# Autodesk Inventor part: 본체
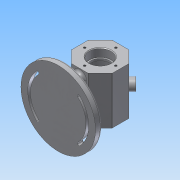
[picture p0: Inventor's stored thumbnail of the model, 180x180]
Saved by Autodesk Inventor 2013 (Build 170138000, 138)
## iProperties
Created: 2017-06
Part Number: 본체
Material: 알루미늄 6061
Document SubType Name: Modeling
Designer: Administrator
Density: 2.71 g/cm^3
Mass: 562.243 g
Surface Area: 566.157 cm^2
Volume: 207.47 cm^3
Author: Administrator
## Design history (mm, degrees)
sketch "스케치1"
  geometry: L1 (12.426, 30)-(30, 12.426); L2 (30, 12.426)-(30, -12.426); L3 (30, -12.426)-(12.426, -30); L4 (12.426, -30)-(-12.426, -30); L5 (-12.426, -30)-(-30, -12.426); L6 (-30, -12.426)-(-30, 12.426); L7 (-30, 12.426)-(-12.426, 30); L8 (-12.426, 30)-(12.426, 30); 2 further points
  constraints: 16 end point, 1 coincident, 1 horizontal, 17 other
  dimensions: "d0" = 60 distance between parallel lines of L3 L7
extrude "돌출1" new body sketch "스케치1" stored distance "d1" = 70; taper "d2" = 0 deg
sketch "스케치2"
  geometry: C1 r 25 at (0, 0); 1 further point
  constraints: 1 centre point, 1 coincident
  dimensions: "d3" = 50 diameter of C1
extrude "돌출2" cut sketch "스케치2" stored distance "d4" = 40; taper "d5" = 0 deg
sketch "스케치3"
  geometry: 2 further points
  constraints: 1 coincident
hole "구멍1" sketch "스케치3" at (0, 0) diameter "d6" = 28; stored, may be unused: countersink angle "d10" = 90 deg, drill point angle "d12" = 0 deg; dims "d7" = 6, "d8" = 32, "d9" = 12, "d11" = 15
node "작업 평면1"
sketch "스케치4"
  geometry: C1 r 8 at (-12.426, 35); 1 further point
  constraints: 1 centre point, 1 coincident
  dimensions: "d14" = 16 diameter of C1
extrude "돌출3" join sketch "스케치4" stored distance "d16" = 40; taper "d17" = 0 deg
node "작업 평면2"
sketch "스케치5"
  geometry: C1 r 55 at (0, 0); 1 further point
  constraints: 1 centre point, 1 coincident
  dimensions: "d19" = 110 diameter of C1
extrude "돌출4" join sketch "스케치5" distance "d20" = 10; taper "d21" = 0 deg
fillet "모깎기1" dims "d22" = 3
sketch "스케치6"
  geometry: C1 r 52 at (0, 0) reference; A1 r 48 centre (0, 0) between (-33.941, 33.941) and (-33.941, -33.941); A2 r 38 centre (0, 0) between (-26.87, 26.87) and (-26.87, -26.87); A3 r 5 centre (-30.406, 30.406) between (-26.87, 26.87) and (-33.941, 33.941); A4 r 5 centre (-30.406, -30.406) between (-33.941, -33.941) and (-26.87, -26.87); A5 r 2 centre (-30.406, -30.406) between (-31.82, -31.82) and (-28.991, -28.991); A6 r 2 centre (-30.406, 30.406) between (-28.991, 28.991) and (-31.82, 31.82); A7 r 41 centre (0, 0) between (-28.991, 28.991) and (-28.991, -28.991); A8 r 45 centre (0, 0) between (-31.82, 31.82) and (-31.82, -31.82)
  constraints: 16 point on circle, 8 centre point, 6 coincident, 6 tangent, 1 vertical alignment
  dimensions: "d23" = 96 diameter of A1; "d24" = 76 diameter of A2; "d25" = 90 deg dimension on C1.centre A4.centre A3.centre; "d26" = 2 radius of A5; "d27" = 2 radius of A6
extrude "돌출5" cut sketch "스케치6" distance "d28" = 3; taper "d29" = 0 deg
extrude "돌출6" cut sketch "스케치6" stored distance "d30" = 3; taper "d31" = 0 deg
sketch "스케치7"
  geometry: L1 (-5, -24)-(5, -24); L2 (5, -24)-(5, 24); L3 (5, 24)-(-5, 24); L4 (-5, 24)-(-5, -24); L5 (-5, -24)-(5, 24); L6 (5, -24)-(-5, 24); C1 r 52 at (0, 0) reference; 2 further points
  constraints: 12 end point, 4 midpoint, 2 horizontal alignment, 2 parallel, 1 horizontal, 1 perpendicular, 4 other
  dimensions: "d32" = 10 distance of L3.end L2.end; "d33" = 48 distance of L2.end L1.end
extrude "돌출7" join sketch "스케치7" stored distance "d34" = 3; taper "d35" = 0 deg
fillet "모깎기2" dims "d36" = 5
sketch "스케치8"
  geometry: C1 r 8 at (0, 0) reference; C2 r 4 at (0, 0)
  constraints: 1 centre point, 1 coincident
  dimensions: "d37" = 8 diameter of C2
extrude "돌출8" cut sketch "스케치8" stored distance "d38" = 3; taper "d39" = 0 deg
chamfer "모따기1" distance "d40" = 1; stored, may be unused: second distance "d41" = 2, angle "d42" = 45 deg
fillet "모깎기3" dims "d43" = 0.3
fillet "모깎기4" dims "d44" = 3
fillet "모깎기5" dims "d45" = 1
sketch "스케치9"
  geometry: 2 further points
  constraints: 1 coincident, 1 other
feature "엠보싱1" sketch "스케치9" dims "d46" = 0.5, "d47" = 0
sketch "스케치10"
  geometry: C1 r 17 at (0, 0) reference; 1 further point
  constraints: 1 vertical alignment
  dimensions: "d48" = 23 distance of C1.centre point (0, 23)
hole "구멍2" sketch "스케치10" at (0, 23) diameter "d49" = 3.242; stored, may be unused: countersink angle "d53" = 90 deg, drill point angle "d55" = 118 deg; dims "d50" = 8, "d51" = 32, "d52" = 12, "d54" = 10
node "솔리드1"
mirror "대칭1"
mirror "대칭2"
pattern_circular "원형 패턴1" dims angle "d57" = 360 deg
mirror "대칭3"
other parameters: "d13" = 7, "d18" = -62
